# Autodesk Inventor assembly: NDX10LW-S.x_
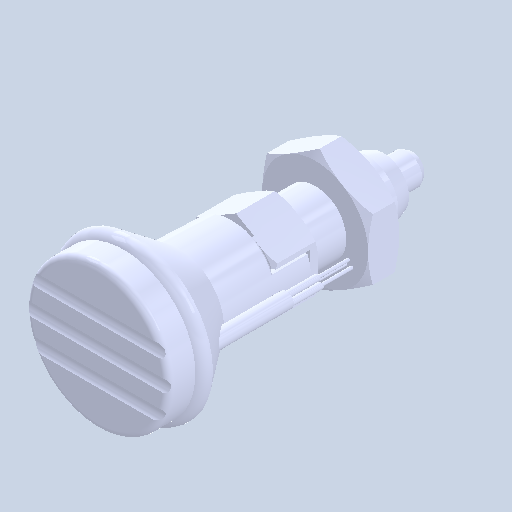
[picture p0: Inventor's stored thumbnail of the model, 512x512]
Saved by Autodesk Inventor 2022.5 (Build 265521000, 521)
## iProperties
Created: 2024-05
Part Number: NDX10LW-S.x_
Document SubType Name: Assembly
Designer: ImaoCorp
Author: ImaoCorp
Sending System: SOLIDWORKS 2022-2022290
MC: AMD64
MC_MODEL: Intel64 Family 6 Model 60 Stepping 3, GenuineIntel
OS: Windows_NT
FRU: Parasolid Version 33.1, build 260,  4-25-2022
FORMAT: text
GUISE: transmit
KEY: FILENDX10LW-S.x_t
DATE: Tue May 21 08:48:08 2024
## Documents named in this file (3)
- X:\14_SW2022-Inv2022\保留中\kipp\KME_データ\n\ndx10lw-s\NDX10LW-S.x_.iam
- X:\14_SW2022-Inv2022\保留中\kipp\KME_データ\n\ndx10lw-s\NDX10LW-S_01.ipt
- X:\14_SW2022-Inv2022\保留中\kipp\KME_データ\n\ndx10lw-s\NDX10LW-S_02.ipt
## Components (2 placed, 2 different names)
1. NDX10LW-S_01
2. NDX10LW-S_02
